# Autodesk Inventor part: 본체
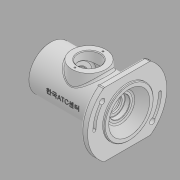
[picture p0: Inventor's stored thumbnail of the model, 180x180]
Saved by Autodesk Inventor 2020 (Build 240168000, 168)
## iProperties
Created: 2022-05
Part Number: 본체
Material: 일반
Document SubType Name: Modeling
Designer: User
Density: 1 g/cm^3
Appearance: 기본값
Author: User
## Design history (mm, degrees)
sketch "스케치1"
  geometry: L1 (0, 0)-(0, 32); L2 (115, 0)-(0, 0); L3 (8, 22.5)-(8, 24); L4 (8, 24)-(11, 24); L5 (11, 24)-(11, 22.5); L6 (11, 22.5)-(22, 22.5); L7 (22, 22.5)-(22, 17.5); L8 (22, 17.5)-(24.25, 17.5); L9 (24.25, 17.5)-(24.25, 18.5); L10 (24.25, 18.5)-(26, 18.5); L11 (26, 18.5)-(26, 17.5); L12 (26, 17.5)-(37, 17.5); L13 (37, 17.5)-(37, 27); L14 (37, 27)-(75, 27); L15 (75, 27)-(75, 17.5); L16 (75, 17.5)-(86, 17.5); L17 (86, 17.5)-(86, 15); L18 (86, 15)-(91, 15); L19 (91, 15)-(91, 11); L20 (91, 11)-(93.7, 11); L21 (0, 32)-(102, 32); L22 (102, 32)-(102, 36); L23 (102, 36)-(115, 36); L24 (115, 36)-(115, 0); L25 (101, 20)-(115, 30); L26 (8, 22.5)-(0, 22.5); L27 (101, 20)-(101, 15); L28 (101, 15)-(93.7, 15); L29 (93.7, 15)-(93.7, 11); L30 (97.35, 15)-(97.35, 0)
  constraints: 60 end point, 22 perpendicular, 5 point on line, 3 vertical, 1 horizontal, 1 midpoint
  dimensions: "d1" = 115 distance of L2.start L1.start; "d3" = 13 distance of L22.end L23.end; "d4" = 72 diameter of L23 L2; "d5" = 64 diameter of L21 L2; "d6" = 60 diameter of L25.end L2; "d7" = 40 diameter of L25.start L2; "d8" = 14 horizontal distance of L25.end L25.start; "d10" = 45 diameter of L26 L2; "d11" = 48 diameter of L4 L2; "d12" = 45 diameter of L6 L2; "d13" = 35 diameter of L8 L2; "d14" = 37 diameter of L10 L2; "d15" = 35 diameter of L12 L2; "d16" = 54 diameter of L14 L2; "d17" = 30 diameter of L18 L2; "d18" = 22 diameter of L20 L2; "d19" = 30 diameter of L28 L2; "d20" = 5 distance of L17.end L18.end; "d21" = 11 distance of L15.end L16.end; "d22" = 38 distance of L13.end L14.end; "d23" = 11 distance of L11.end L12.end; "d24" = 8 distance of L3.start L26.end; "d25" = 3 distance of L3.end L4.end; "d26" = 22 distance from line of L6.end L1; "d27" = 4 distance between parallel lines of L11 L7; "d28" = 1.75 distance of L9.end L10.end; "d29" = 2.7 distance of L19.end L20.end
revolve "회전1" stored, may be unused: angle "d30" = 90 deg
node "작업 평면1"
sketch "스케치2"
  geometry: L1 (0, 0)-(0, 58); L2 (-47, 0)-(-47, 33.985); L3 (0, 0)-(-47, 0); L4 (47, 0)-(47, 33.985); L5 (47, 0)-(47, -33.985); L6 (-47, 0)-(-47, -33.985); A1 r 58 centre (0, 0) between (-47, -33.985) and (47, -33.985); A2 r 58 centre (0, 0) between (47, 33.985) and (-47, 33.985); 1 further point
  constraints: 12 end point, 5 point on circle, 4 symmetric about line, 2 centre point, 1 coincident, 1 parallel, 1 perpendicular, 1 vertical
  dimensions: "d33" = 47 distance between parallel lines of L1 L2; "d34" = 58 radius of A2
extrude "돌출1" join sketch "스케치2" distance "d35" = 10; taper "d36" = 0 deg
revolve "회전2" stored, may be unused: angle "d37" = 90 deg
sketch "스케치3"
  geometry: L1 (0, 0)-(-48, 0); L2 (0, 0)-(-48.362, -48.362); A1 r 48 centre (0, 0) between (-48, 0) and (-33.941, -33.941); A2 r 48 centre (0, 0) between (-48, 0) and (-33.941, -33.941); 1 further point
  constraints: 4 end point, 4 point on circle, 2 centre point, 1 coincident, 1 concentric, 1 horizontal, 1 point on line
  dimensions: "d38" = 96 diameter of A1; "d39" = 45 deg angle of L2 L1
node "작업 평면2"
sketch "스케치4"
  geometry: L1 (0, 32)-(0, -32) reference; C1 r 25 at (-56, 0); 2 further points
  constraints: 1 centre point, 1 horizontal alignment, 1 midpoint
  dimensions: "d42" = 50 diameter of C1; "d43" = 56 distance from line of C1.centre L1
extrude "돌출2" join sketch "스케치4" stored distance "d44" = 13; taper "d45" = 5 deg
sketch "스케치5"
  geometry: C1 r 25 at (0, 0) reference; C2 r 16 at (0, 0); 1 further point
  constraints: 1 centre point, 1 coincident
  dimensions: "d46" = 32 diameter of C2
extrude "돌출3" cut sketch "스케치5" stored distance "d47" = 13; taper "d48" = 0 deg
sketch "스케치6"
  geometry: L1 (-33.985, -47)-(33.985, -47) reference; L2 (33.985, 47)-(-33.985, 47) reference; L3 (0, 0)-(-48, 0); L4 (0, 0)-(-36.77, -30.854); L5 (0, 0)-(36.77, 30.854); L6 (0, 0)-(48, 0); C1 r 36 at (0, 0) reference; A1 r 58 centre (0, 0) between (33.985, -47) and (33.985, 47) reference; A2 r 58 centre (0, 0) between (-33.985, 47) and (-33.985, -47) reference; A3 r 48 centre (0, 0) between (-48, 0) and (-36.77, -30.854); 3 further points
  constraints: 8 end point, 4 point on circle, 3 coincident, 2 horizontal, 1 centre point
  dimensions: "d49" = 96 diameter of A3; "d50" = 40 deg angle of L4 L3; "d51" = 40 deg angle of L6 L5
hole "구멍1" sketch "스케치6" at (-36.77, -30.854), (36.77, 30.854) diameter "d52" = 8; stored, may be unused: countersink angle "d56" = 90 deg, drill point angle "d58" = 118 deg; dims "d53" = 8, "d54" = 8, "d55" = 4.4, "d57" = 10
sketch "스케치7"
  geometry: L1 (33.985, -47)-(-33.985, -47) reference; L2 (-33.985, 47)-(33.985, 47) reference; L3 (0, 0)-(-48, 0); L4 (0, 0)-(48, 0); C1 r 4 at (36.77, -30.854) reference; C2 r 4 at (-36.77, 30.854) reference; C3 r 36 at (0, 0) reference; A1 r 58 centre (0, 0) between (-33.985, 47) and (-33.985, -47) reference; A2 r 58 centre (0, 0) between (33.985, -47) and (33.985, 47) reference; A3 r 48 centre (0, 0) between (-48, 0) and (48, 0); A4 r 48 centre (0, 0) between (-36.77, 30.854) and (-48, 0); A5 r 50.25 centre (0, 0) between (-38.494, 32.3) and (-50.25, 0); A6 r 45.75 centre (0, 0) between (-35.047, 29.408) and (-45.75, 0); A7 r 2.25 centre (-36.77, 30.854) between (-35.047, 29.408) and (-38.494, 32.3); A8 r 2.25 centre (-48, 0) between (-50.25, 0) and (-45.75, 0); A9 r 48 centre (0, 0) between (36.77, -30.854) and (48, 0); A10 r 48 centre (0, 0) between (36.77, -30.854) and (48, 0); A11 r 50.25 centre (0, 0) between (38.494, -32.3) and (50.25, 0); A12 r 45.75 centre (0, 0) between (35.047, -29.408) and (45.75, 0); A13 r 2.25 centre (36.77, -30.854) between (35.047, -29.408) and (38.494, -32.3); A14 r 2.25 centre (48, 0) between (50.25, 0) and (45.75, 0); 3 further points
  constraints: 24 point on circle, 12 centre point, 9 tangent, 4 end point, 3 concentric, 2 horizontal, 1 coincident
  dimensions: "d59" = 96 diameter of A3; "d60" = 2.25 radius of A8; "d63" = 2.25 radius of A14
  node "투영된 루프3"
extrude "돌출4" cut sketch "스케치7" extent not by distance; stored distance "d61" = 0; taper "d62" = 0 deg
extrude "돌출5" cut sketch "스케치7" extent not by distance; stored distance "d64" = 10; taper "d65" = 0 deg
sketch "스케치8"
  geometry: L1 (0, 0)-(0, 20.5); L2 (0, 0)-(0, -20.5); C1 r 16 at (0, 0) reference; C2 r 25 at (0, 0) reference; A1 r 20.5 centre (0, 0) between (0, 20.5) and (0, -20.5); 3 further points
  constraints: 4 end point, 3 coincident, 2 point on circle, 1 centre point, 1 point on line, 1 vertical
  dimensions: "d66" = 41 diameter of A1
hole "구멍2" sketch "스케치8" at (0, 20.5), (0, -20.5) diameter "d67" = 2.459; stored, may be unused: countersink angle "d71" = 82 deg, drill point angle "d73" = 118 deg; dims "d68" = 6, "d69" = 3.023, "d70" = 4400, "d72" = 8
feature "스레드1" dims "d74" = 8, "d75" = 0
fillet "모깎기1" dims "d76" = 3
chamfer "모따기1" distance "d77" = 1; stored, may be unused: second distance "d78" = 2, angle "d79" = 45 deg
chamfer "모따기2" distance "d80" = 1; stored, may be unused: second distance "d81" = 2, angle "d82" = 45 deg
fillet "모깎기2" dims "d83" = 3
fillet "모깎기3" dims "d84" = 0.6
fillet "모깎기4" dims "d85" = 0.5
fillet "모깎기6" dims "d90" = 3
fillet "모깎기7" dims "d91" = 3
fillet "모깎기8" dims "d92" = 3
chamfer "모따기4" distance "d93" = 1; stored, may be unused: second distance "d94" = 2, angle "d95" = 45 deg
node "작업 평면3"
sketch "스케치9"
  geometry: L1 (26.906, 4.949)-(73.094, 4.949); L2 (73.094, 4.949)-(73.094, -4.949); L3 (73.094, -4.949)-(26.906, -4.949); L4 (26.906, -4.949)-(26.906, 4.949); L5 (26.906, 4.949)-(73.094, -4.949); L6 (73.094, 4.949)-(26.906, -4.949); L7 (112, 46.4)-(112, -46.4) reference; 3 further points
  constraints: 4 end point, 2 midpoint, 1 horizontal alignment, 2 other
  dimensions: "d97" = 62 distance from line of point (50, 0) L7
feature "엠보싱1" sketch "스케치9" dims "d1" = 115, "d8" = 14, "d98" = 0.5, "d99" = 0
sketch "스케치10"
  geometry: L1 (-33, 44)-(33, 44) reference; L2 (33, -44)-(-33, -44) reference; C1 r 35 at (0, 0) reference; C2 r 48 at (0, 0); A1 r 55 centre (0, 0) between (-33, 44) and (-33, -44) reference; A2 r 55 centre (0, 0) between (33, -44) and (33, 44) reference; A3 r 45.75 centre (0, 0) between (45.75, 0) and (37.033, 26.862) reference; A4 r 4 centre (36.77, 30.854) between (40.58, 29.636) and (37.033, 26.862) reference; A5 r 50.25 centre (0, 0) between (50.25, 0) and (40.58, 29.636) reference; A6 r 2.25 centre (48, 0) between (45.75, 0) and (50.25, 0) reference; A7 r 45.75 centre (0, 0) between (-45.75, 0) and (-37.033, -26.862) reference; A8 r 4 centre (-36.77, -30.854) between (-40.58, -29.636) and (-37.033, -26.862) reference; A9 r 50.25 centre (0, 0) between (-50.25, 0) and (-40.58, -29.636) reference; A10 r 2.25 centre (-48, 0) between (-45.75, 0) and (-50.25, 0) reference; A11 r 48 centre (0, 0) between (-48, 0) and (-36.77, -30.854); A12 r 52 centre (0, 0) between (-52, 0) and (-39.834, -33.425); A13 r 44 centre (0, 0) between (-44, 0) and (-33.706, -28.283); A14 r 4 centre (-48, 0) between (-44, 0) and (-52, 0); A15 r 4 centre (-36.77, -30.854) between (-39.834, -33.425) and (-33.706, -28.283); A16 r 48 centre (0, 0) between (48, 0) and (36.77, 30.854); A17 r 52 centre (0, 0) between (52, 0) and (39.834, 33.425); A18 r 44 centre (0, 0) between (44, 0) and (33.706, 28.283); A19 r 4 centre (48, 0) between (44, 0) and (52, 0); A20 r 4 centre (36.77, 30.854) between (39.834, 33.425) and (33.706, 28.283); 5 further points
  constraints: 20 point on circle, 11 centre point, 8 tangent, 4 concentric, 1 coincident
  dimensions: "d100" = 96 diameter of C2
extrude "돌출6" cut sketch "스케치10" distance "d101" = 4.4; taper "d102" = 0 deg
fillet "모깎기9" dims "d103" = 3
chamfer "모따기5" distance "d104" = 0.7; stored, may be unused: second distance "d105" = 2, angle "d106" = 30 deg
node "솔리드1"
node "투영된 루프1"
node "투영된 루프2"
node "투영된 루프4"
node "투영된 루프5"
feature "A9D066F2-1C7D-4E18-AEED-F7BC21143FA4" dims "d74" = 8, "d75" = 0
other parameters: "d31" = -3, "d32" = 116, "d41" = 38, "d96" = 32
